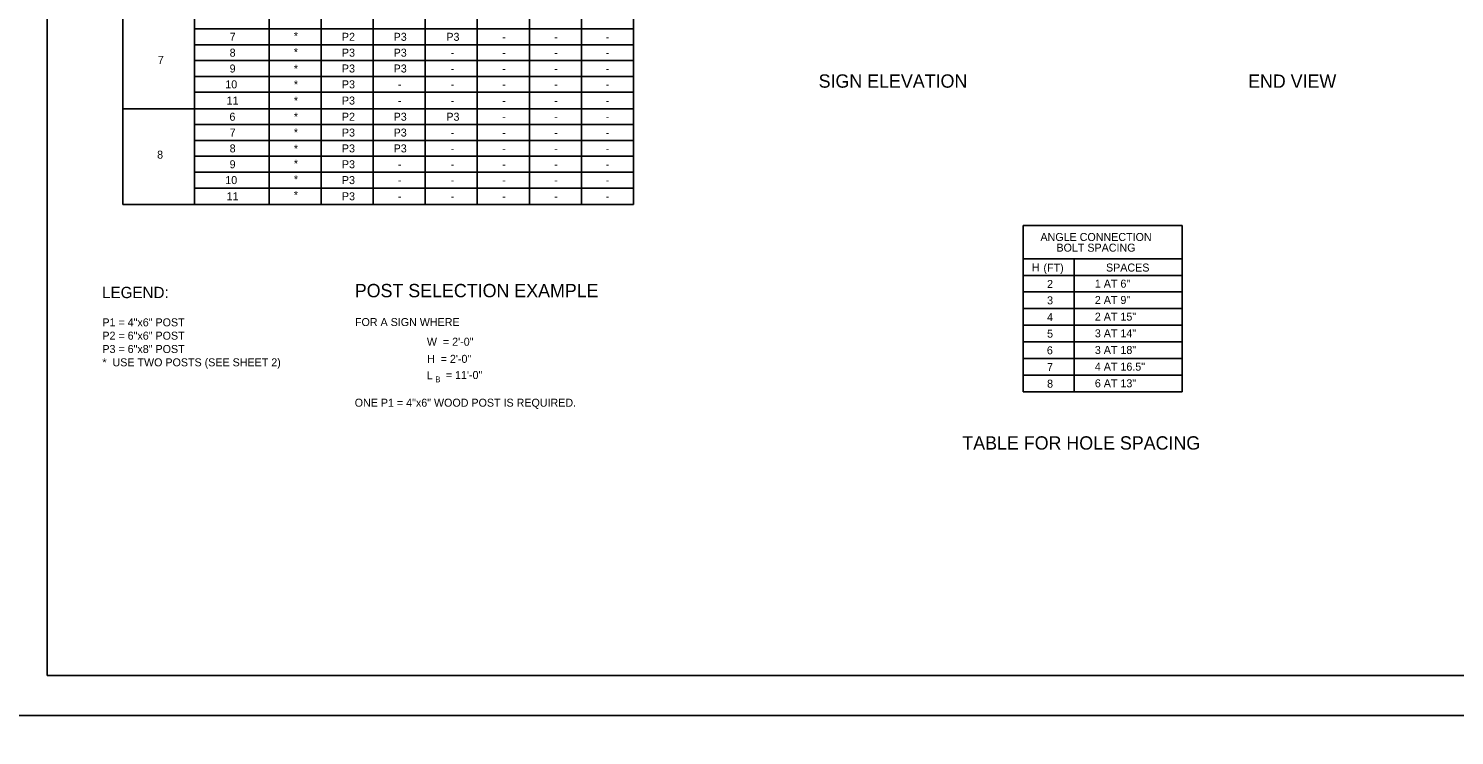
# Model space of a CAD drawing. Extents: x -2340 to 628, y -879 to 309.
# Drawn here: x -1925 to -1391, y -292 to -27 of the extents above; entities that cross this region are included whole.
import ezdxf

# ---------------------------------------------------------------- set-up
doc = ezdxf.new("R2010")
doc.units = 0
for name, color, linetype in [('Level 1', 7, 'Continuous'), ('Level 2', 7, 'Continuous'), ('Level 3', 7, 'Continuous'), ('Level 4', 7, 'Continuous'), ('PLT-BNDY', 7, 'Continuous')]:
    doc.layers.add(name, color=color, linetype=linetype)

msp = doc.modelspace()

# ---------------------------------------------------------------- linework, layer by layer
at = {"layer": 'Level 1'}
for p, q in [((-1918.39, 294.44), (-1918.39, -269.56)), ((-1698.58, -92.95), (-1698.58, 184.44)), ((-1863.14, -92.95), (-1863.14, 176.76)), ((-1835.13, -92.95), (-1835.13, 176.76)), ((-1132.39, -269.56), (-1918.39, -269.56)), ((-1918.39, -269.56), (-1332.39, -269.56))]:
    msp.add_line(p, q, dxfattribs=at)
at = {"layer": 'Level 2'}
for p, q in [((-1889.94, -92.95), (-1889.94, 158.42)), ((-1815.62, -92.95), (-1815.62, 158.42)), ((-1796.12, -92.95), (-1796.12, 158.42)), ((-1776.61, -92.95), (-1776.61, 158.42)), ((-1757.1, -92.95), (-1757.1, 158.42)), ((-1737.59, -92.95), (-1737.59, 158.42)), ((-1718.09, -92.95), (-1718.09, 158.42)), ((-1863.14, -27.07), (-1698.58, -27.07)), ((-1863.14, -33.01), (-1698.58, -33.01)), ((-1863.14, -38.95), (-1698.58, -38.95)), ((-1863.14, -44.89), (-1698.58, -44.89)), ((-1863.14, -50.83), (-1698.58, -50.83)), ((-1889.94, -57.04), (-1698.58, -57.04)), ((-1863.14, -62.98), (-1698.58, -62.98)), ((-1863.14, -68.92), (-1698.58, -68.92)), ((-1863.14, -74.86), (-1698.58, -74.86)), ((-1863.14, -80.8), (-1698.58, -80.8)), ((-1863.14, -86.74), (-1698.58, -86.74)), ((-1889.94, -92.95), (-1698.58, -92.95)), ((-1492.93, -100.86), (-1552.43, -100.86)), ((-1552.43, -163.23), (-1552.43, -100.86)), ((-1492.93, -163.23), (-1492.93, -100.86)), ((-1492.93, -113.36), (-1552.43, -113.36)), ((-1533.33, -163.05), (-1533.33, -113.17)), ((-1492.93, -119.61), (-1552.43, -119.61)), ((-1492.93, -125.73), (-1552.43, -125.73)), ((-1492.93, -131.98), (-1552.43, -131.98)), ((-1492.93, -138.23), (-1552.43, -138.23)), ((-1492.93, -144.48), (-1552.43, -144.48)), ((-1492.93, -150.73), (-1552.43, -150.73)), ((-1492.93, -156.98), (-1552.43, -156.98)), ((-1492.93, -163.23), (-1552.43, -163.23))]:
    msp.add_line(p, q, dxfattribs=at)
at = {"layer": 'PLT-BNDY'}
for points in [[(-1958.39, 309.44), (-1117.39, 309.44), (-1117.39, -284.56), (-1958.39, -284.56)], [(-1958.39, -284.56), (-1117.39, -284.56), (-1117.39, -878.56), (-1958.39, -878.56)]]:
    msp.add_lwpolyline(points, close=True, dxfattribs=at)

# ---------------------------------------------------------------- texts
at = {"layer": 'Level 1'}
for s, height, p in [('7', 3, (-1876.87, -40.22)), ('8', 3, (-1877.13, -75.72)), ('FOR A SIGN WHERE ', 3, (-1802.96, -138.51)), ('W  = 2\'-0"', 3, (-1776, -145.89)), ('H  = 2\'-0"', 3, (-1775.95, -152.31)), ('L', 3, (-1776, -158.47)), ('B', 2.2, (-1772.88, -159.61)), (' = 11\'-0"', 3, (-1770.02, -158.38)), ('ONE P1 = 4"x6" WOOD POST IS REQUIRED.', 3, (-1803.06, -168.76))]:
    msp.add_text(s, height=height, dxfattribs=at).set_placement(p)
at = {"layer": 'Level 2'}
for s, height, p in [('7', 3, (-1849.94, -31.54)), ('*', 3, (-1825.88, -31.22)), ('P2', 3, (-1807.86, -31.54)), ('P3', 3, (-1788.47, -31.54)), ('P3', 3, (-1768.7, -31.54)), ('-', 3, (-1747.81, -31.54)), ('-', 3, (-1728.25, -31.54)), ('-', 3, (-1708.96, -31.54)), ('8', 3, (-1849.94, -37.48)), ('*', 3, (-1825.88, -37.28)), ('P3', 3, (-1807.86, -37.48)), ('P3', 3, (-1788.47, -37.48)), ('-', 3, (-1767.08, -37.48)), ('-', 3, (-1747.81, -37.48)), ('-', 3, (-1728.25, -37.48)), ('-', 3, (-1708.96, -37.48)), ('9', 3, (-1849.95, -43.42)), ('*', 3, (-1825.88, -43.48)), ('P3', 3, (-1807.86, -43.42)), ('P3', 3, (-1788.47, -43.42)), ('-', 3, (-1767.08, -43.42)), ('-', 3, (-1747.81, -43.42)), ('-', 3, (-1728.25, -43.42)), ('-', 3, (-1708.96, -43.42)), ('10', 3, (-1851.57, -49.36)), ('*', 3, (-1825.88, -49.38)), ('P3', 3, (-1807.86, -49.36)), ('-', 3, (-1786.85, -49.36)), ('-', 3, (-1767.08, -49.36)), ('-', 3, (-1747.81, -49.36)), ('-', 3, (-1728.25, -49.36)), ('-', 3, (-1708.96, -49.36)), ('11', 3, (-1851.09, -55.43)), ('*', 3, (-1825.88, -55.44)), ('P3', 3, (-1807.86, -55.43)), ('6', 3, (-1850.02, -61.51)), ('*', 3, (-1825.88, -61.49)), ('P2', 3, (-1807.86, -61.51)), ('P3', 3, (-1788.47, -61.51)), ('-', 3, (-1786.85, -55.43)), ('P3', 3, (-1768.7, -61.51)), ('-', 3, (-1767.08, -55.43)), ('-', 3, (-1747.81, -55.43)), ('-', 3, (-1728.25, -55.43)), ('-', 3, (-1708.96, -55.43)), ('-', 3, (-1747.81, -61.51)), ('-', 3, (-1728.25, -61.51)), ('-', 3, (-1708.96, -61.51)), ('7', 3, (-1849.94, -67.45)), ('*', 3, (-1825.88, -67.39)), ('P3', 3, (-1807.86, -67.45)), ('P3', 3, (-1788.47, -67.45)), ('-', 3, (-1767.08, -67.45)), ('-', 3, (-1747.81, -67.45)), ('-', 3, (-1728.25, -67.45)), ('-', 3, (-1708.96, -67.45)), ('8', 3, (-1849.94, -73.39)), ('*', 3, (-1825.88, -73.45)), ('P3', 3, (-1807.86, -73.39)), ('P3', 3, (-1788.47, -73.39)), ('-', 3, (-1767.08, -73.39)), ('-', 3, (-1747.81, -73.39)), ('-', 3, (-1728.25, -73.39)), ('-', 3, (-1708.96, -73.39)), ('9', 3, (-1849.95, -79.33)), ('*', 3, (-1825.88, -79.05)), ('P3', 3, (-1807.86, -79.33)), ('-', 3, (-1786.85, -79.33)), ('-', 3, (-1767.08, -79.33)), ('-', 3, (-1747.81, -79.33)), ('-', 3, (-1728.25, -79.33)), ('-', 3, (-1708.96, -79.33)), ('10', 3, (-1851.57, -85.27)), ('*', 3, (-1825.88, -84.95)), ('P3', 3, (-1807.86, -85.27)), ('-', 3, (-1786.85, -85.27)), ('-', 3, (-1767.08, -85.27)), ('-', 3, (-1747.81, -85.27)), ('-', 3, (-1728.25, -85.27)), ('-', 3, (-1708.96, -85.27)), ('11', 3, (-1851.09, -91.34)), ('*', 3, (-1825.88, -90.85)), ('P3', 3, (-1807.86, -91.34)), ('-', 3, (-1786.85, -91.34)), ('-', 3, (-1767.08, -91.34)), ('-', 3, (-1747.81, -91.34)), ('-', 3, (-1728.25, -91.34)), ('-', 3, (-1708.96, -91.34)), ('POST SELECTION EXAMPLE', 5, (-1803.04, -127.71))]:
    msp.add_text(s, height=height, dxfattribs=at).set_placement(p)
at = {"layer": 'Level 3'}
for s, height, p in [('SIGN ELEVATION', 5, (-1629.15, -49.12)), ('END VIEW', 5, (-1468.17, -49.17)), ('ANGLE CONNECTION', 3, (-1546, -106.61)), ('BOLT SPACING', 3, (-1540, -110.61)), ('H', 3, (-1549.26, -117.97)), ('(FT)', 3, (-1544.87, -118.13)), ('SPACES', 3, (-1521.42, -118.07)), ('2', 3, (-1543.51, -124.23)), ('1 AT 6"', 3, (-1525.6, -124.11)), ('LEGEND:', 4.25, (-1897.75, -128.04)), ('3', 3, (-1543.51, -130.36)), ('2 AT 9"', 3, (-1525.6, -130.23)), ('4', 3, (-1543.51, -136.61)), ('2 AT 15"', 3, (-1525.6, -136.48)), ('5', 3, (-1543.51, -142.86)), ('3 AT 14"', 3, (-1525.6, -142.73)), ('6', 3, (-1543.59, -149.11)), ('3 AT 18"', 3, (-1525.6, -148.98)), ('7', 3, (-1543.51, -155.36)), ('4 AT 16.5"', 3, (-1525.6, -155.23)), ('8', 3, (-1543.51, -161.61)), ('6 AT 13"', 3, (-1525.6, -161.48)), ('TABLE FOR HOLE SPACING', 5, (-1575.29, -184.85))]:
    msp.add_text(s, height=height, dxfattribs=at).set_placement(p)
at = {"layer": 'Level 4'}
for s, p in [('P1 = 4"x6" POST', (-1897.65, -138.62)), ('P2 = 6"x6" POST', (-1897.65, -143.62)), ('P3 = 6"x8" POST', (-1897.65, -148.62)), ('*  USE TWO POSTS (SEE SHEET 2)', (-1897.65, -153.62))]:
    msp.add_text(s, height=3, dxfattribs=at).set_placement(p)

doc.saveas('drawing.dxf')
